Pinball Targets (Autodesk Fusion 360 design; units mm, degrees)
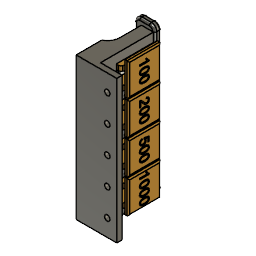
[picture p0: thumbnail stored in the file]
sketch "Microswitch" plane through (0, 0, 0) normal (0, 0, 1) x axis (1, 0, 0)
  line L1 (-6.5, 4.9) -> (-2.5, 4.9)
  line L2 (-6.5, -3) -> (-2.5, -3)
  line L3 (-6.5, -3.1) -> (-6.5, -3)
  line L4 (-6.5, -3.1) -> (-2.5, -3.1)
  line L5 (8.2, -2) -> (8, -2)
  line L6 (-6.5, 12.9) -> (-2.5, 12.9)
  line L7 (7, 15) -> (-2.5, 15)
  line L8 (-2.5, -5) -> (7, -5)
  line L9 (7, -5) -> (7, 15)
  line L10 (-6.5, 4.9) -> (-6.5, 5)
  line L11 (-6.5, 5) -> (-2.5, 5)
  line L12 (-2.5, 15) -> (-2.5, -5)
  line L13 (-6.5, 12.9) -> (-6.5, 13)
  line L14 (-6.5, 13) -> (-2.5, 13)
  line L15 (8.2, -1) -> (7, -1)
  line L16 (7, -2) -> (8.2, -2)
  line L17 (10.6515, 10.2573) -> (8.2, -2)
  line L18 (10.4946, 10.4728) -> (8.2, -1)
  line L19 (11.3967, 15.1981) -> (11.3967, 14.9835)
  circle C1 centre (0, 10) radius 1.25
  circle C2 centre (0, 0) radius 1.25
  arc A1 centre (11.1438, 12.7096) radius 2.5013 clockwise from (11.3967, 15.1981) to (10.6515, 10.2573)
  arc A2 centre (10.9456, 12.7281) radius 2.3 clockwise from (11.3967, 14.9835) to (10.4946, 10.4728)
  point P13 (0, 0)
  point P21 (0, 0)
  point P7 (-2.5, -3)
  point P15 (-2.5, 13)
  point P4 (-2.5, 5)
  point P12 (7, -1)
  point P10 (7, -2)
  coincident P13 P21
  horizontal L8
  perpendicular L8 L12
  perpendicular L7 L12
  coincident P7 L12
  perpendicular L2 L12
  coincident P15 L12
  perpendicular L12 L14
  midpoint P4 L12
  perpendicular L11 L12
  perpendicular L6 L13
  perpendicular L1 L10
  perpendicular L3 L4
  coincident P12 L9
  coincident P10 L9
  perpendicular L9 L16
  vertical L19
extrude "Extrude1" new body sketch "Microswitch" profile of L5 L7 L8 L9 C1 L12 C2 L15 L16 L17 L18 A1 A2 L19 along normal blind 6 bodies "Microswitch"
extrude "Extrude2" add sketch "Microswitch" profile of L1 L2 L3 L4 L6 L10 L11 L12 L13 L14 blind 4 from offset 1
sketch "Target Bracket" plane through (0, 0, 0) normal (0, 0, 1) x axis (1, 0, 0)
  line L1 (0.5, 3) -> (0.5, 0)
  line L2 (-3, 24) -> (-3, -7)
  line L3 (10, -7) -> (10, -4)
  line L4 (8, 17) -> (-3, 17)
  line L5 (-3, 17) -> (-3, 24)
  line L6 (3.5, 13) -> (3.5, 10)
  line L7 (39, -4) -> (8, -4)
  line L8 (3.5, 0) -> (3.5, -3)
  line L9 (39, -7) -> (39, -10)
  line L10 (8, -4) -> (8, 24)
  line L11 (39, -7) -> (39, -4)
  line L12 (3.5, 3) -> (3.5, 0)
  line L13 (3.5, 10) -> (3.5, 7)
  line L14 (39, -10) -> (-3, -10)
  line L15 (-3, -7) -> (39, -7)
  line L16 (8, 24) -> (-3, 24)
  line L17 (-3, -10) -> (-3, -7)
  line L18 (0.5, 13) -> (0.5, 10)
  line L19 (0.5, 0) -> (0.5, -3)
  line L20 (0.5, 10) -> (0.5, 7)
  arc A1 centre (2, 13) radius 1.5 clockwise from (0.5, 13) to (3.5, 13)
  arc A2 centre (2, 3) radius 1.5 clockwise from (0.5, 3) to (3.5, 3)
  arc A3 centre (2, 7) radius 1.5 clockwise from (3.5, 7) to (0.5, 7)
  arc A4 centre (2, -3) radius 1.5 clockwise from (3.5, -3) to (0.5, -3)
  point P16 (-3, 24)
  point P12 (8, 17)
  point P9 (10, -4)
  point P34 (10, -7)
  point P23 (39, -7)
  perpendicular L7 L11
  perpendicular L11 L15
  perpendicular L2 L15
  perpendicular L10 L16
  coincident P16 L16
  perpendicular L5 L16
  coincident P12 L10
  perpendicular L4 L10
  vertical L18
  vertical L6
  vertical L20
  vertical L13
  vertical L1
  vertical L12
  vertical L19
  vertical L8
  coincident P9 L7
  coincident P34 L15
  perpendicular L3 L15
  perpendicular L15 L17
  perpendicular L14 L17
  coincident P23 L15
sketch "Target Tile" plane through (7, 0, 0) normal (1, 0, 0) x axis (0, 1, 0)
  line L1 (12, -12) -> (-12, -12)
  line L2 (12, 12) -> (12, -12)
  line L3 (-12, 12) -> (12, 12)
  line L4 (-12, -12) -> (-12, 12)
  line L5 (7.5, -2.3) -> (7.5, 2.3)
  line L6 (2, -2.3) -> (7.5, -2.3)
  line L7 (2, 2.3) -> (2, -2.3)
  line L8 (7.5, 2.3) -> (2, 2.3)
  line L9 (2, 4.5) -> (2, 2.3)
  line L10 (8.5, 4.5) -> (2, 4.5)
  line L11 (8.5, -4.5) -> (8.5, 4.5)
  line L12 (2, -4.5) -> (8.5, -4.5)
  line L13 (2, -2.3) -> (2, -4.5)
  line L14 (8.5, 8) -> (-14, 8)
  line L15 (8.5, 4.5) -> (8.5, 8)
  line L16 (-14, 4.5) -> (-14, 8)
  line L17 (2, 4.5) -> (-14, 4.5)
  line L18 (8.5, -8) -> (8.5, -4.5)
  line L19 (-14, -8) -> (8.5, -8)
  line L20 (-14, -4.5) -> (-14, -8)
  line L21 (2, -4.5) -> (-14, -4.5)
  point P16 (8.5, 4.5)
  perpendicular L1 L2
  perpendicular L2 L3
  perpendicular L1 L4
  perpendicular L5 L6
  perpendicular L5 L8
  perpendicular L8 L9
  perpendicular L9 L10
  perpendicular L6 L13
  coincident L10 P16
  perpendicular L10 L15
  perpendicular L14 L16
  perpendicular L1 L18
  perpendicular L19 L20
extrude "Extrude3" new body sketch "Target Tile" along normal blind 3.5 bodies "Target Tile 1"
move "Move1"
extrude "Extrude4" add sketch "Target Tile" profile of L4 L10 L12 L14 L15 L16 L17 L18 L19 L20 L21 against normal blind 9
extrude "Extrude5" add sketch "Target Tile" profile of L5 L6 L8 L9 L10 L11 L12 L13 against normal blind 3
extrude "Extrude6" add sketch "Target Tile" profile of L5 L6 L7 L8 L9 L10 L11 L12 L13 blind -1.2 from offset -3
fillet "Fillet2" radius 1
fillet "Fillet3" radius 1
sketch "Target Frame Layout" plane through (7, 0, 0) normal (1, 0, 0) x axis (0, 1, 0)
  line L1 (12, -62) -> (-12, -62)
  line L2 (-12, -38) -> (12, -38)
  line L3 (-12, -62) -> (-12, -38)
  line L4 (12, -38) -> (12, -62)
  line L5 (12, -87) -> (-12, -87)
  line L6 (-12, -63) -> (12, -63)
  line L7 (12, -63) -> (12, -87)
  line L8 (-12, -87) -> (-12, -63)
  line L9 (-12, 12) -> (12, 12)
  line L10 (-12, -12) -> (-12, 12)
  line L11 (12, 12) -> (12, -12)
  line L12 (12, -12) -> (-12, -12)
  line L13 (12, -13) -> (12, -37)
  line L14 (-12, -37) -> (-12, -13)
  line L15 (12, -37) -> (-12, -37)
  line L16 (-12, -13) -> (12, -13)
  line L17 (-10.2, -33.4) -> (12, -33.4)
  line L18 (12, -41.6) -> (-10.2, -41.6)
  line L19 (-10.2, -8.4) -> (12, -8.4)
  line L20 (-10.2, -8.4) -> (-10.2, 8.4)
  line L21 (12, -16.6) -> (-10.2, -16.6)
  line L22 (12, 8.4) -> (-10.2, 8.4)
  line L23 (-10.2, -33.4) -> (-10.2, -16.6)
  line L24 (12, -66.6) -> (-10.2, -66.6)
  line L25 (-10.2, -58.4) -> (-10.2, -41.6)
  line L26 (-10.2, -83.4) -> (-10.2, -66.6)
  line L27 (-10.2, -58.4) -> (12, -58.4)
  line L28 (-10.2, -83.4) -> (12, -83.4)
  line L29 (-12, 8.4) -> (-10.2, 8.4)
  line L30 (-12, -8.4) -> (-10.2, -8.4)
  line L31 (-12, -16.6) -> (-10.2, -16.6)
  line L32 (-12, -33.4) -> (-10.2, -33.4)
  line L33 (-12, -41.6) -> (-10.2, -41.6)
  line L34 (-12, -58.4) -> (-10.2, -58.4)
  line L35 (-12, -66.6) -> (-10.2, -66.6)
  line L36 (-12, -83.4) -> (-10.2, -83.4)
  point P27 (-10.2, -66.6)
  point P30 (12, -83.4)
  point P31 (12, -66.6)
  point P32 (12, -58.4)
  point P33 (12, -41.6)
  point P34 (12, -33.4)
  point P35 (12, -16.6)
  point P36 (12, -8.4)
  point P37 (12, 8.4)
  point P38 (-12, 8.4)
  perpendicular L2 L4
  perpendicular L6 L7
  perpendicular L9 L11
  perpendicular L13 L16
  perpendicular L11 L19
  collinear L20 L23
  collinear L23 L25
  coincident P27 L25
  collinear L25 L26
  coincident L7 P30
  coincident L7 P31
  coincident L4 P32
  coincident L4 P33
  coincident L13 P34
  coincident L13 P35
  coincident L11 P36
  coincident L11 P37
  coincident L10 P38
  perpendicular L10 L29
sketch "Target Frame 9mm deck" plane through (0, 0, 0) normal (1, 0, 0) x axis (0, 1, 0)
  line L1 (13, -90) -> (13, -83.4)
  line L2 (-17, -90) -> (13, -90)
  line L3 (-17, -83.4) -> (-17, -90)
  line L4 (13, -83.4) -> (-17, -83.4)
  line L5 (-17, -58.4) -> (-17, -66.6)
  line L6 (13, -66.6) -> (13, -58.4)
  line L7 (13, -66.6) -> (-17, -66.6)
  line L8 (13, -58.4) -> (-17, -58.4)
  line L9 (13, -33.4) -> (-17, -33.4)
  line L10 (13, -41.6) -> (-17, -41.6)
  line L11 (13, -41.6) -> (13, -33.4)
  line L12 (-17, -33.4) -> (-17, -41.6)
  line L13 (13, -16.6) -> (13, -8.4)
  line L14 (13, -16.6) -> (-17, -16.6)
  line L15 (13, -8.4) -> (-17, -8.4)
  line L16 (-17, -8.4) -> (-17, -16.6)
  line L17 (13, 8.4) -> (13, 15)
  line L18 (-17, 8.4) -> (13, 8.4)
  line L19 (13, 15) -> (-17, 15)
  line L20 (-17, 15) -> (-17, 8.4)
  line L21 (-14.2, -4.5) -> (-17, -4.5)
  line L22 (-17, 4.5) -> (-14.2, 4.5)
  line L23 (-14.2, 8.4) -> (-14.2, 4.5)
  line L24 (-17, -83.4) -> (-17, 8.4)
  line L25 (-14.2, -83.4) -> (-14.2, -66.6)
  line L26 (-14.2, -58.4) -> (-14.2, -41.6)
  line L27 (-14.2, -8.4) -> (-14.2, 4.5)
  line L28 (-14.2, -33.4) -> (-14.2, -16.6)
  line L29 (-17, -20.5) -> (-14.2, -20.5)
  line L30 (-14.2, -79.5) -> (-17, -79.5)
  line L31 (-17, -70.5) -> (-14.2, -70.5)
  line L32 (-23, 15) -> (-17, 15)
  line L33 (-23, -90) -> (-23, 15)
  line L34 (-17, -90) -> (-23, -90)
  line L35 (-17, -54.5) -> (-14.2, -54.5)
  line L36 (-17, -45.5) -> (-14.2, -45.5)
  line L37 (-17, -29.5) -> (-14.2, -29.5)
  line L38 (-27, 15) -> (-23, 15)
  line L39 (-27, -90) -> (-27, 15)
  line L40 (-23, -90) -> (-27, -90)
  point P25 (-14.2, -83.4)
  point P26 (-14.2, -58.4)
  point P27 (-14.2, -66.6)
  point P28 (-14.2, -33.4)
  point P29 (-14.2, -41.6)
  point P30 (-14.2, -8.4)
  point P31 (-14.2, -16.6)
  point P32 (-17, 4.5)
  point P33 (-17, -4.5)
  point P45 (-14.2, 8.4)
  point P42 (-17, -79.5)
  point P39 (-17, -70.5)
  point P46 (-17, -54.5)
  point P47 (-17, -45.5)
  point P48 (-17, -29.5)
  point P34 (-17, -20.5)
  point P22 (-14.2, -4.5)
  point P36 (-14.2, -20.5)
  point P35 (-14.2, -29.5)
  point P38 (-14.2, -45.5)
  point P37 (-14.2, -54.5)
  point P41 (-14.2, -70.5)
  point P40 (-14.2, -79.5)
  perpendicular L1 L2
  perpendicular L2 L3
  perpendicular L6 L7
  perpendicular L6 L8
  perpendicular L10 L11
  perpendicular L9 L11
  perpendicular L13 L14
  perpendicular L13 L15
  perpendicular L17 L18
  perpendicular L18 L20
  perpendicular L19 L23
  perpendicular L4 L24
  coincident L4 P25
  coincident L8 P26
  coincident L7 P27
  collinear L25 L27
  coincident L9 P28
  coincident L10 P29
  collinear L26 L27
  coincident L15 P30
  coincident L14 P31
  collinear L27 L28
  coincident L24 P32
  coincident L24 P33
  perpendicular L20 L32
  perpendicular L32 L33
  perpendicular L3 L34
  coincident L18 P45
  coincident L24 P42
  perpendicular L24 L30
  coincident L24 P39
  coincident L24 P46
  perpendicular L24 L35
  coincident L24 P47
  perpendicular L24 L36
  coincident L24 P48
  coincident L24 P34
  coincident P22 L27
  perpendicular L21 L27
  coincident L28 P36
  perpendicular L28 L29
  coincident L28 P35
  perpendicular L28 L37
  coincident L26 P38
  perpendicular L26 L36
  coincident L26 P37
  coincident L25 P41
  perpendicular L25 L31
  coincident L25 P40
  perpendicular L33 L38
  perpendicular L38 L39
move "Move2"
extrude "Extrude7" new body sketch "Target Frame 9mm deck" profile of L1 L2 L3 L4 L5 L6 L7 L8 L9 L10 L11 L12 L13 L14 L15 L16 L17 L18 L19 L20 L21 L22 L28 L23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 along normal blind 4 bodies "Mounting Bracket 9mm deck"
fillet "Fillet5" radius 2
sketch "Target Retainer" plane through (-2, 0, 0) normal (-1, 0, 0) x axis (0, -1, 0)
  line L1 (14, -9.5) -> (14, -4.5)
  line L2 (-8.5, -9.5) -> (14, -9.5)
  line L3 (-8.5, -4.5) -> (-8.5, -9.5)
  line L4 (14, -4.5) -> (-8.5, -4.5)
  line L5 (14, 9.5) -> (-8.5, 9.5)
  line L6 (-8.5, 9.5) -> (-8.5, 4.5)
  line L7 (14, 4.5) -> (14, 9.5)
  line L8 (-8.5, 4.5) -> (14, 4.5)
  perpendicular L1 L2
extrude "Extrude8" add sketch "Target Retainer" against normal blind 2.5
chamfer "Chamfer1" distance 1.5
chamfer "Chamfer2" distance 1.5
chamfer "Chamfer4" distance 1.5
sketch "Target Frame Bracket" plane through (0, 0, 0) normal (1, 0, 0) x axis (0, 1, 0)
  line L1 (-17, -9.9) -> (13, -9.9)
  line L2 (13, -15.1) -> (-17, -15.1)
  line L3 (13, -9.9) -> (13, -15.1)
  line L4 (-17, -9.9) -> (-17, -15.1)
  line L5 (13, 9.9) -> (-17, 9.9)
  line L6 (-17, 15) -> (-17, 9.9)
  line L7 (-17, 15) -> (13, 15)
  line L8 (13, 15) -> (13, 9.9)
  line L9 (-17, -34.9) -> (13, -34.9)
  line L10 (-17, -34.9) -> (-17, -40.1)
  line L11 (13, -40.1) -> (-17, -40.1)
  line L12 (13, -34.9) -> (13, -40.1)
  line L13 (-17, -59.9) -> (-17, -65.1)
  line L14 (13, -65.1) -> (-17, -65.1)
  line L15 (-17, -59.9) -> (13, -59.9)
  line L16 (13, -59.9) -> (13, -65.1)
  line L17 (-17, -84.9) -> (-17, -90.1)
  line L18 (13, -84.9) -> (13, -90.1)
  line L19 (13, -90.1) -> (-17, -90.1)
  line L20 (-17, -84.9) -> (13, -84.9)
  perpendicular L1 L3
  perpendicular L1 L4
  perpendicular L7 L8
  perpendicular L6 L7
  perpendicular L9 L12
  perpendicular L9 L10
  perpendicular L15 L16
  perpendicular L13 L15
  perpendicular L18 L20
  perpendicular L17 L20
extrude "Extrude9" add sketch "Target Frame Bracket" profile of L1 L2 L3 L4 L9 L10 L11 L12 L13 L14 L15 L16 L17 L18 L19 L20 against normal blind 10
sketch "Target Retainer Flange 9mm deck" plane through (0, 0, -9.9) normal (0, 0, 1) x axis (-1, 0, 0)
  line L1 (4.9, -13) -> (10, -13)
  line L2 (10, 17) -> (10, -13)
  line L3 (4.9, 17) -> (10, 17)
  line L4 (4.9, -13) -> (4.9, 14.2)
  line L5 (4.9, 1.5) -> (10, 1.5)
  line L6 (4.9, -5) -> (10, -5)
  line L7 (4.9, 4.5) -> (10, 4.5)
  line L8 (4.9, 11) -> (10, 11)
  line L9 (0, 14.2) -> (4.9, 14.2)
  line L10 (0, 17) -> (0, 14.2)
  line L11 (4.9, 17) -> (0, 17)
  line L12 (10, 27.0022) -> (10, 17)
  line L13 (0, 27.0022) -> (10, 27.0022)
  line L14 (0, 17) -> (0, 27.0022)
  point P6 (4.9, 1.5)
  point P7 (4.9, -5)
  point P8 (10, -5)
  point P9 (10, 1.5)
  point P11 (4.9, 4.5)
  point P13 (4.9, 11)
  horizontal L1
  perpendicular L1 L2
  perpendicular L2 L3
  perpendicular L1 L4
  coincident L4 P6
  coincident L4 P7
  coincident L2 P8
  coincident L2 P9
  coincident L4 P11
  perpendicular L4 L7
  coincident L4 P13
  perpendicular L4 L8
  perpendicular L3 L12
  perpendicular L12 L13
  parallel L10 L14
extrude "Extrude10" add sketch "Target Retainer Flange 9mm deck" profile of L1 L2 L3 L4 L5 L6 along normal blind 6.7
extrude "Extrude11" cut sketch "Target Retainer Flange 9mm deck" profile of L2 L4 L5 L6 L7 L8 along normal blind 4 and against normal blind 6
extrude "Extrude12" add sketch "Target Retainer Flange 9mm deck" profile of L1 L2 L3 L4 L5 L6 L7 L8 blind 6.7 from offset -25
extrude "Extrude13" cut sketch "Target Retainer Flange 9mm deck" profile of L2 L4 L5 L6 L7 L8 blind 4 second side blind 6 from offset -25
extrude "Extrude14" add sketch "Target Retainer Flange 9mm deck" profile of L1 L2 L3 L4 L5 L6 L7 L8 blind 6.7 from offset -50
extrude "Extrude15" cut sketch "Target Retainer Flange 9mm deck" profile of L2 L4 L5 L6 L7 L8 blind 4 second side blind 6 from offset -50
extrude "Extrude16" add sketch "Target Retainer Flange 9mm deck" profile of L1 L2 L3 L4 L5 L6 L7 L8 blind 6.7 from offset -75
extrude "Extrude17" cut sketch "Target Retainer Flange 9mm deck" profile of L2 L4 L5 L6 L7 L8 blind 4 second side blind 6 from offset -75
sketch "Target Retainer Drill" plane through (0, 0, 3) normal (0, 0, 1) x axis (-1, 0, 0)
  line L1 (-3.6515, -2.2573) -> (-1.2, 10)
  line L2 (-4.3967, -6.9835) -> (-4.3967, -7.1981)
  line L3 (-1.2, 9) -> (-3.4946, -2.4728)
  line L4 (0, 9) -> (-1.2, 9)
  line L5 (0, -7) -> (0, 9)
  line L6 (9.5, -7) -> (0, -7)
  line L7 (9.5, 13) -> (9.5, -7)
  line L8 (0, 13) -> (9.5, 13)
  line L9 (0, 10) -> (0, 13)
  line L10 (-1.2, 10) -> (0, 10)
  circle C1 centre (7, -2) radius 1.25
  circle C2 centre (7, 8) radius 1.25
  arc A1 centre (-4.1438, -4.7096) radius 2.5013 clockwise from (-4.3967, -7.1981) to (-3.6515, -2.2573)
  arc A2 centre (-3.9456, -4.7281) radius 2.3 clockwise from (-4.3967, -6.9835) to (-3.4946, -2.4728)
  circle C3 centre (7, -2) radius 1.25
  circle C4 centre (7, 8) radius 1.25
  circle C5 centre (7, -2) radius 2.25
  circle C6 centre (7, 8) radius 2.25
  concentric C1 C3
  concentric C2 C4
  concentric C3 C5
extrude "Extrude18" cut sketch "Target Retainer Drill" profile of C1 C2 C3 C4 against normal blind 100
sketch "Target Frame Bracket Brace" plane through (0, 0, -3.2) normal (0, 0, 1) x axis (-1, 0, 0)
  line L1 (10, 17) -> (10, 14.2)
  line L2 (0, 17) -> (10, 17)
  line L3 (0, 14.2) -> (10, 14.2)
  line L4 (0, 17) -> (0, 14.2)
  perpendicular L1 L3
  parallel L1 L4
extrude "Extrude19" add sketch "Target Frame Bracket Brace" against normal blind 75 and along normal blind 18.2
extrude "Extrude20" new body sketch "Target Retainer Drill" profile of C1 C2 C3 C4 C5 C6 along normal blind 3 bodies "Bolt 1", "Bolt 2"
extrude "Extrude21" add sketch "Target Frame 9mm deck" profile of L33 L38 L39 L40 along normal blind 20
extrude "Extrude22" add sketch "Target Frame Bracket" profile of L5 L6 L7 L8 against normal blind 4
extrude "Extrude23" add sketch "Target Retainer Flange 9mm deck" profile of L3 L11 L12 L13 L14 along normal blind 24.9 and against normal blind 80.2
fillet "Fillet7" radius 10
sketch "Target Frame Mounting Drill" plane through (0, -27, 0) normal (0, -1, 0) x axis (1, 0, 0)
  circle C1 centre (13, 2.5) radius 2
  circle C2 centre (13, -77.5) radius 2
  circle C3 centre (13, -17.5) radius 2
  circle C4 centre (13, -37.5) radius 2
  circle C5 centre (13, -57.5) radius 2
extrude "Extrude24" cut sketch "Target Frame Mounting Drill" against normal blind 5
fillet "Fillet8" radius 5
copy_paste_bodies "CopyPasteBodies1"
copy_paste_bodies "CopyPasteBodies2"
copy_paste_bodies "CopyPasteBodies3"
move "Move3"
move "Move4"
move "Move5"
sketch "Scores" plane through (10.5, 0, 0) normal (1, 0, 0) x axis (0, 1, 0)
  dimension "d99" = 7
  dimension "d100" = "'100'"
  dimension "d101" = 7
  dimension "d102" = "'200'"
  dimension "d103" = 7
  dimension "d104" = "'500'"
  dimension "d105" = 7
  dimension "d106" = "'1000'"
extrude "Extrude25" cut sketch "Scores" against normal blind 0.4
sketch "Top" plane through (0, 13, 0) normal (0, 1, 0) x axis (-1, 0, 0)
  line L1 (12, -92) -> (-3, -92)
  line L2 (12, 17) -> (12, -92)
  line L3 (-3, 17) -> (12, 17)
  line L4 (-3, -92) -> (-3, 17)
  line L5 (0, 9.9) -> (-1.5, 8.4)
  line L6 (4, 9.9) -> (0, 9.9)
  line L7 (4, 15) -> (4, 9.9)
  line L8 (-4, 15) -> (4, 15)
  line L9 (-4, 8.4) -> (-4, 15)
  line L10 (-1.5, 8.4) -> (-4, 8.4)
  circle C1 centre (7, -87) radius 1.4
  circle C2 centre (7, -12.5) radius 1.4
  circle C3 centre (7, -12.5) radius 4
  circle C4 centre (7, -87) radius 4
  circle C5 centre (7, -87) radius 1.9
  circle C6 centre (7, -12.5) radius 1.9
  concentric C1 C5
  concentric C3 C6
  dimension "d110" diameter C3 = 8
  dimension "d111" diameter C4 = 8
  dimension "d126" diameter C5 = 3.8
  dimension "d127" diameter C6 = 3.8
extrude "Extrude26" new body sketch "Top" profile of C3 C4 C5 C6 along normal blind 2 bodies "Top"
extrude "Extrude27" new body sketch "Top" profile of L1 L2 L3 L4 C3 C4 C5 C6 blind 5 from offset 2
extrude "Extrude28" cut sketch "Top" profile of C1 C2 C3 C4 blind 10 from offset 4
fillet "Fillet9" radius 4
fillet "Fillet10" radius 1.5
fillet "Fillet11" radius 1.5
combine "Combine1"
extrude "Extrude29" cut sketch "Top" profile of C1 C2 against normal blind 10
sketch "Target Frame 12mm deck" plane through (0, 0, 0) normal (1, 0, 0) x axis (0, 1, 0)
  line L1 (-17, -45.5) -> (-14.2, -45.5)
  line L2 (-17, -83.4) -> (-17, 8.4)
  line L3 (-26, -90) -> (-30, -90)
  line L4 (-30, -90) -> (-30, 15)
  line L5 (-17, -90) -> (13, -90)
  line L6 (-26, -90) -> (-26, 15)
  line L7 (-17, -54.5) -> (-14.2, -54.5)
  line L8 (-17, -90) -> (-26, -90)
  line L9 (13, -66.6) -> (13, -58.4)
  line L10 (-17, -58.4) -> (-17, -66.6)
  line L11 (13, -41.6) -> (13, -33.4)
  line L12 (13, -41.6) -> (-17, -41.6)
  line L13 (-17, -83.4) -> (-17, -90)
  line L14 (-17, -33.4) -> (-17, -41.6)
  line L15 (-14.2, -58.4) -> (-14.2, -41.6)
  line L16 (13, -83.4) -> (-17, -83.4)
  line L17 (13, -90) -> (13, -83.4)
  line L18 (13, -58.4) -> (-17, -58.4)
  line L19 (-17, -70.5) -> (-14.2, -70.5)
  line L20 (-14.2, -79.5) -> (-17, -79.5)
  line L21 (13, -66.6) -> (-17, -66.6)
  line L22 (-14.2, -83.4) -> (-14.2, -66.6)
  line L23 (-17, -8.4) -> (-17, -16.6)
  line L24 (-14.2, -33.4) -> (-14.2, -16.6)
  line L25 (-17, 8.4) -> (13, 8.4)
  line L26 (-17, -29.5) -> (-14.2, -29.5)
  line L27 (13, -33.4) -> (-17, -33.4)
  line L28 (-26, 15) -> (-17, 15)
  line L29 (13, -8.4) -> (-17, -8.4)
  line L30 (-17, 4.5) -> (-14.2, 4.5)
  line L31 (13, -16.6) -> (13, -8.4)
  line L32 (-14.2, -4.5) -> (-17, -4.5)
  line L33 (-17, -20.5) -> (-14.2, -20.5)
  line L34 (-14.2, -8.4) -> (-14.2, 4.5)
  line L35 (-17, 15) -> (-17, 8.4)
  line L36 (-30, 15) -> (-26, 15)
  line L37 (13, 15) -> (-17, 15)
  line L38 (13, 8.4) -> (13, 15)
  line L39 (13, -16.6) -> (-17, -16.6)
  line L40 (-14.2, 8.4) -> (-14.2, 4.5)
  point P47 (-14.2, -83.4)
  point P46 (-14.2, -58.4)
  point P12 (-14.2, -66.6)
  point P11 (-14.2, -33.4)
  point P13 (-14.2, -41.6)
  point P10 (-14.2, -8.4)
  point P17 (-14.2, -16.6)
  point P16 (-17, 4.5)
  point P48 (-17, -4.5)
  point P28 (-14.2, 8.4)
  point P33 (-17, -79.5)
  point P38 (-17, -70.5)
  point P29 (-17, -54.5)
  point P37 (-17, -45.5)
  point P42 (-17, -29.5)
  point P49 (-17, -20.5)
  point P21 (-14.2, -4.5)
  point P51 (-14.2, -20.5)
  point P50 (-14.2, -29.5)
  point P31 (-14.2, -45.5)
  point P30 (-14.2, -54.5)
  point P41 (-14.2, -70.5)
  point P36 (-14.2, -79.5)
  perpendicular L5 L17
  perpendicular L5 L13
  perpendicular L9 L21
  perpendicular L9 L18
  perpendicular L11 L12
  perpendicular L11 L27
  perpendicular L31 L39
  perpendicular L29 L31
  perpendicular L25 L38
  perpendicular L25 L35
  perpendicular L37 L40
  perpendicular L2 L16
  coincident P47 L16
  coincident P46 L18
  coincident P12 L21
  collinear L22 L34
  coincident P11 L27
  coincident P13 L12
  collinear L15 L34
  coincident P10 L29
  coincident P17 L39
  collinear L24 L34
  coincident P16 L2
  coincident P48 L2
  perpendicular L28 L35
  perpendicular L6 L28
  perpendicular L8 L13
  coincident P28 L25
  coincident P33 L2
  perpendicular L2 L20
  coincident P38 L2
  coincident P29 L2
  perpendicular L2 L7
  coincident P37 L2
  perpendicular L1 L2
  coincident P42 L2
  coincident P49 L2
  coincident P21 L34
  perpendicular L32 L34
  coincident P51 L24
  perpendicular L24 L33
  coincident P50 L24
  perpendicular L24 L26
  coincident P31 L15
  perpendicular L1 L15
  coincident P30 L15
  coincident P41 L22
  perpendicular L19 L22
  coincident P36 L22
  perpendicular L6 L36
  perpendicular L4 L36
extrude "Extrude30" new body sketch "Target Frame 12mm deck" profile of L3 L4 L6 L36 along normal blind 20 and against normal blind 10 bodies "Mounting Bracket 12mm deck"
extrude "Extrude31" add sketch "Target Frame 12mm deck" profile of L1 L2 L5 L6 L7 L8 L9 L10 L11 L12 L13 L14 L15 L16 L17 L18 L19 L20 L21 L22 L23 L24 L25 L26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 along normal blind 4
extrude "Extrude32" add sketch "Target Frame 12mm deck" profile of L1 L2 L6 L7 L8 L10 L12 L13 L14 L15 L16 L18 L19 L20 L21 L22 L23 L24 L25 L26 L27 L28 L29 L30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 against normal blind 10
extrude "Extrude33" cut sketch "Target Frame Mounting Drill" along normal blind 10 and against normal blind 10
extrude "Extrude34" add sketch "Target Frame Bracket Brace" along normal blind 18.2 and against normal blind 86.8
extrude "Extrude35" add sketch "Target Frame Bracket" against normal blind 10
extrude "Extrude36" add sketch "Target Retainer Flange 9mm deck" profile of L1 L2 L3 L4 L5 L6 L7 L8 L9 L10 L11 along normal blind 6.7
extrude "Extrude37" add sketch "Target Retainer Flange 9mm deck" profile of L1 L2 L3 L4 L5 L6 L7 L8 L9 L10 L11 blind 6.7 from offset -25
extrude "Extrude38" add sketch "Target Retainer Flange 9mm deck" profile of L1 L2 L3 L4 L5 L6 L7 L8 L9 L10 L11 blind 6.7 from offset -50
extrude "Extrude39" add sketch "Target Retainer Flange 9mm deck" profile of L1 L2 L3 L4 L5 L6 L7 L8 L9 L10 L11 blind 6.7 from offset -75
extrude "Extrude40" add sketch "Target Retainer Flange 9mm deck" profile of L2 L4 L5 L6 L7 L8 blind 2.7 from offset 4
extrude "Extrude41" add sketch "Target Retainer Flange 9mm deck" profile of L2 L4 L5 L6 L7 L8 blind 2.7 from offset -21
extrude "Extrude42" add sketch "Target Retainer Flange 9mm deck" profile of L2 L4 L5 L6 L7 L8 blind 2.7 from offset -46
extrude "Extrude43" add sketch "Target Retainer Flange 9mm deck" profile of L2 L4 L5 L6 L7 L8 blind 2.7 from offset -71
extrude "Extrude45" cut sketch "Target Retainer Flange 9mm deck" profile of L2 L4 L5 L6 L7 L8 against normal blind 10
extrude "Extrude46" cut sketch "Target Retainer Flange 9mm deck" profile of L2 L4 L5 L6 L7 L8 blind -10 from offset -25
extrude "Extrude47" cut sketch "Target Retainer Flange 9mm deck" profile of L2 L4 L5 L6 L7 L8 blind -10 from offset -50
extrude "Extrude48" cut sketch "Target Retainer Flange 9mm deck" profile of L2 L4 L5 L6 L7 L8 blind -10 from offset -75
extrude "Extrude49" cut sketch "Target Retainer Drill" profile of C1 C2 C3 C4 against normal blind 200
fillet "Fillet12" radius 5
chamfer "Chamfer5" distance 1.5
extrude "Extrude50" cut sketch "Target Retainer Flange 9mm deck" profile of L1 L2 L4 L5 L6 L7 L8 blind 20 from offset 10
fillet "Fillet13" radius 9
extrude "Extrude51" cut sketch "Top" profile of C1 C2 against normal blind 12
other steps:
base_feature "Base Feature1" bodies "Target Tile 1", "Target Tile 2"
base_feature "Base Feature2" bodies "Target Tile 2", "Target Tile 3"
base_feature "Base Feature3" bodies "Target Tile 3", "Target Tile 4"
named bodies: "Microswitch", "Target Tile 1", "Mounting Bracket 9mm deck", "Bolt 1", "Bolt 2", "Target Tile 2", "Target Tile 3", "Target Tile 4", "Top", "Mounting Bracket 12mm deck"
